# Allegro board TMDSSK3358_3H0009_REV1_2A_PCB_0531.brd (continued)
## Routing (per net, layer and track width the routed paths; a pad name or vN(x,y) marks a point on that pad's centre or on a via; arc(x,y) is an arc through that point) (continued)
MMC1_D2: length 76.1
  LY6_SIG2 w0.127: v2(68.74,31.41) 68.6,31.41 68.2,31.01 67.78,31.01 67.55,30.78 67.55,30.35 67.4,30.2 67.4,28.76 66.83,28.19 66.83,25.9 66.78,25.85 66.78,25.81 63.37,22.39 62.7,22.39 61.29,20.99 60.15,20.99 59.04,19.88 54.45,19.88 52.16,22.17 49.02,22.17 35.53,22.17 32.66,25.05 32.66,25.28 29.71,28.22 29.71,29.57 28.4,30.88 28.4,33.53 26.75,35.19 23.25,35.19 22.92,34.86 22.92,33.22 22.54,32.84 v1(15.37,32.84)
  BOTTOM w0.14: R185.1 16.21,36.14 14.9,34.84 A1.14 14.9,33.31 v1(15.37,32.84) ; U26.R8 v2(68.74,31.41)
MMC1_D3: length 75.3
  LY6_SIG2 w0.127: v1(20.53,35.13) 19.95,34.54 18.57,34.54 18.31,34.29 18.31,33.76 18.57,33.5 21.69,33.5 22.26,34.07 22.26,35.47 22.64,35.85 28.05,35.85 29.85,34.05 29.85,31.69 31.74,29.8 31.74,29.12 32.58,28.29 33.34,28.29 34.13,27.5 34.13,25.34 36.63,22.83 44.46,22.83 45.24,23.61 45.61,23.61 46.38,22.83 53,22.83 55.21,20.62 57.03,20.62 58.31,21.91 61.28,21.91 63.59,24.22 64.32,24.22 65.67,25.56 65.67,27.23 66.33,27.89 66.33,31.04 66.69,31.41 v2(67.94,31.41)
  BOTTOM w0.14: A1.19 19.9,34.5 v1(20.53,35.13) 19.9,35.75 19.9,35.9 R182.1 ; U26.T8 v2(67.94,31.41)
Net_4: length 0.5
  BOTTOM w0.127: 104.75,30.17 104.89,30.17 105.14,29.92
Net_5: length 0.5
  BOTTOM w0.127: 104.75,30.93 104.89,30.93 105.16,31.21
Net_6: length 0.5
  BOTTOM w0.127: 58.77,14.63 58.91,14.63 59.17,14.38
Net_7: length 0.5
  BOTTOM w0.127: 58.77,15.38 58.91,15.38 59.19,15.66
Net_14: length 0.6
  BOTTOM w0.14: 78.74,30.21 78.74,30.21 v2(79.14,29.81)
NON_REM1: length 3.3
  BOTTOM w0.14: U16.13 42.82,53.15 42.6,52.93 R118.1 R119.2
NON_REM2: length 10.2
  TOP w0.14: v1(35.97,58.65) 37.58,58.65 39,57.22 39.97,57.22 v1(40.04,57.29) 40.04,56.37 R12.2 R13.1
  BOTTOM w0.14: TP1.1 34.97,58.65 v1(35.97,58.65) ; v1(40.04,57.29) U16.19
PHY2_LED_10/100N: length 4.2
  BOTTOM w0.14: C237.1 59.49,34.65 58.65,35.48 58.02,35.48 57.43,36.08 U24.26
PHY2_LED_1000N: length 44.2
  TOP w0.14: v1(63.37,57.96) 62.82,58.52 R9.1 ; R61.2 59.31,36.28 59.55,36.53 59.55,36.54 ; 59.55,36.54 59.51,36.58 58.42,36.58 C81.1 ; 59.55,36.54 v1(59.55,36.7)
  LY6_SIG2 w0.127: v1(63.37,57.96) 62.71,58.62 61.66,58.62 58.77,55.73 57.79,55.73 55.26,53.2 55.26,50.18 50.93,45.86 50.93,41.74 52.11,40.56 52.11,39.76 54.03,37.85 57.46,37.85 58.6,36.7 v1(59.55,36.7)
  BOTTOM w0.14: U24.24 58.7,36.93 59.05,36.58 59.51,36.58 59.55,36.54 v1(59.55,36.7)
PHY2_LED_ACTN: length 40.9
  TOP w0.14: C68.1 59.44,37.47 v1(59.52,37.38) 60.07,36.83 60.07,36.2 R62.2 ; v1(62.1,57.96) 61.68,58.39 R8.1
  LY6_SIG2 w0.127: v1(59.52,37.38) 59.51,37.38 59.47,37.34 58.7,37.34 56.93,39.12 54.03,39.12 53.75,39.4 53.32,39.83 53.2,39.95 52.89,40.26 52.89,41.93 51.31,43.51 51.31,45.7 55.64,50.03 55.64,52.99 57.79,55.14 59.28,55.14 v1(62.1,57.96)
  BOTTOM w0.14: v1(59.52,37.38) 59.52,37.67 59.24,37.95 U24.23
PHY_LED_10/100N: length 6.5
  BOTTOM w0.14: U23.26 97.81,36.13 98.46,35.48 99.32,35.48 100.81,33.99 102.02,33.99 C240.1
PHY_LED_1000N: length 39.5
  TOP w0.14: R7.1 94.47,62.43 94.47,58.4 96.91,55.95 99.69,55.95 102.11,53.53 v1(102.11,52.07) ; R60.2 100.79,36.37 100.59,36.58 v1(99.95,36.58)
  LY3_SIG1 w0.127: v1(99.95,36.58) 100.5,36.58 102.11,38.19 102.11,48.64 103.36,49.89 103.36,52.16 103.1,52.42 102.46,52.42 v1(102.11,52.07)
  BOTTOM w0.14: U23.24 99.56,37.55 99.83,37.28 99.83,36.7 v1(99.95,36.58) 100.62,36.58 100.79,36.4 C229.1
PHY_LED_ACTN: length 51
  TOP w0.14: v1(100.48,37.19) 100.48,37.24 100.71,37.47 R53.2 ; v1(102.92,51.98) 102.9,51.99 102.9,53.9 99.94,56.86 96.88,56.86 95.26,58.48 95.26,63.83 93.41,65.68 84.15,65.68 R6.1
  LY3_SIG1 w0.127: v1(100.48,37.19) 101.68,38.39 101.68,50.74 v1(102.92,51.98)
  BOTTOM w0.14: U23.23 99.72,37.95 v1(100.48,37.19) 101,37.19 R53.2
PHY_PPS2/GPIO: length 2
  BOTTOM w0.14: U24.22 59.31,38.35 R181.1
PHY_PPS/GPIO: length 2.5
  BOTTOM w0.14: U23.22 100.01,38.35 100.26,38.1 100.77,38.1 R176.1
PLLFILT: length 2
  TOP w0.14: v1(43.82,60.2) 43.87,60.14 C7.1
  BOTTOM w0.14: U16.25 v1(43.82,60.2)
PMIC_GPIO: length 2.4
  TOP w0.14: v1(109.98,37.21) 110.19,37.41 110.41,37.41 R59.2
  BOTTOM w0.14: v1(109.98,37.21) 109.98,37.34 110.49,37.84 U25.39
PMIC_GPIO_RTC: length 4.1
  BOTTOM w0.14: U19.6 112.53,52.83 R108.1 C191.1 R107.1
PMIC_I2C_SCL: length 3
  BOTTOM w0.14: U25.9 115.05,42.79 115.44,43.19 R139.1
PMIC_I2C_SDA: length 3.3
  BOTTOM w0.14: U25.8 114.65,42.86 115.04,43.26 115.04,44.34 R140.1
PMIC_INT1: length 15.7
  TOP w0.14: v1(106.4,42.9) 107.03,42.27 108.33,42.27 108.78,42.72 108.78,43.25 108.97,43.43 109.6,43.43 R28.1
  BOTTOM w0.14: R128.1 106.31,44.22 105.89,43.79 105.89,43.3 106.28,42.9 v1(106.4,42.9) 106.6,42.7 106.6,41.76 107.24,41.12 107.75,41.12 108.55,40.33 109.87,40.33 109.96,40.24 U25.45
PMIC_PWRHOLD: length 4.9
  TOP w0.14: R27.1 108.9,44.15 v1(108.81,44.07)
  BOTTOM w0.14: U25.1 110.59,42.22 108.81,43.99 v1(108.81,44.07)
PMIC_RESETOUTN: length 43
  TOP w0.14: R49.2 109.35,38.34 v1(109.73,37.96)
  LY6_SIG2 w0.127: v1(109.73,37.96) 110.03,37.66 110.17,37.66 110.8,37.03 110.8,34.81 110.23,34.25 109.6,34.25 107.3,31.94 103.53,31.94 103.02,32.45 101.82,33.65 93.43,33.65 92.25,34.82 90.98,34.82 88.77,37.03 88.77,37.47 88.37,37.86 87.43,37.86 86.91,37.34 v2(84.96,37.34)
  BOTTOM w0.14: v1(109.73,37.96) 110.15,37.96 110.43,38.24 U25.40 ; U26.B15 79.95,37.83 82.13,37.83 82.63,38.33 83.22,38.33 84.33,37.21 84.84,37.21 v2(84.96,37.34)
PMIC_SLEEP: length 7.2
  BOTTOM w0.14: TP9.1 106.04,34.35 108.46,34.35 109.11,35 109.11,35.57 109.24,35.7 110.58,37.04 U25.37
PMICSR_I2C_SCL: length 3.6
  BOTTOM w0.14: R137.1 117.73,45.06 117.25,44.58 117.25,44.06 115.85,42.66 U25.11
PMICSR_I2C_SDA: length 3.3
  BOTTOM w0.14: U25.10 115.45,42.72 116.59,43.86 R138.1
PWR_SMPS1: length 1.8
  BOTTOM w0.203: 112.25,35.61 U25.35
  BOTTOM w0.381: 112.25,34.46 112.25,35.61
PWR_SMPS1_FB: length 35.7
  LY6_SIG2 w0.254: v1(99.45,26.11) 101.11,27.76 108.15,27.76 v1(113.66,33.27)
  BOTTOM w0.203: U25.32 113.45,34.54 113.75,34.24 114.15,34.24 114.43,33.97 R201.2
  BOTTOM w0.254: v1(99.45,26.11) 98.25,24.91 96.13,24.91 95.38,25.65 94.23,25.65 92.96,24.38 89.28,24.38 v1(88.14,23.24) 87.5,22.61 R223.2
  BOTTOM w0.381: R201.2 113.87,33.48 v1(113.66,33.27)
PWR_SMPS2: length 0.6
  BOTTOM w0.203: U25.42 110.43,39.04
PWR_SWIO: length 1.1
  BOTTOM w0.203: 117.61,41.04 U25.14
  BOTTOM w0.254: 118.14,41.04 117.61,41.04
PWR_VDDIO: length 4.1
  BOTTOM w0.14: U25.12 116.25,42.54 118.02,44.31 R144.2
REFIN_DDR: length 3.7
  TOP w0.14: R93.1 C171.1 R95.1 87.78,5.61 U14.1
RESETN: length 3.5
  BOTTOM w0.14: R106.1 C189.1 39.94,55.63 40.6,56.29 U16.17
RGMII1_INT: length 95.5
  TOP w0.14: v2(67.94,30.61) 66.73,29.4 66.73,26.62 67.2,26.14 68.3,26.14 69.03,25.41 69.03,24.89 68.88,24.74 68.88,20.18 69.35,19.72 80.07,19.72 80.29,19.93 81.17,20.81 83.04,20.81 85.89,20.81 86.36,21.28 93.3,21.28 93.57,21.54 93.57,21.55 93.67,21.64 93.74,21.72 94.49,22.46 95.39,22.46 v1(95.76,22.83)
  LY3_SIG1 w0.127: v1(95.76,22.83) 94.6,22.83 94.32,23.12 94.32,25.57 94.83,26.08 98.31,26.08 98.73,25.66 103.07,25.66 105.92,28.51 105.92,32.06 106.69,32.84 106.69,33.35 106.06,33.98 106.06,36.95 105.73,37.28 105.73,38.95 107.76,40.98 107.76,43.96 108.47,44.67 108.47,45.69 107.76,46.4 107.76,48.97 103.98,52.75 100.36,52.75 v1(97.47,49.86)
  BOTTOM w0.14: U26.U6 v2(67.94,30.61) ; R122.2 v1(97.47,49.86)
RGMII1_TXCLK: length 5.7
  BOTTOM w0.14: U26.K18 73.14,40.19 73.28,40.33 73.28,40.37 73.3,40.39 73.3,42.95 73.42,43.07 73.42,43.9 73.84,44.32 R134.2
RGMII1_TXD0: length 6.6
  BOTTOM w0.14: R135.2 72.83,42.91 72.89,42.85 72.89,42.84 73.06,42.66 73.06,40.49 72.77,40.2 72.77,39.38 U26.K17
RGMII1_TXD1: length 11.4
  LY6_SIG2 w0.127: v1(78.05,43.05) 78.05,41.5 77.61,41.05 76.25,41.05 76.06,40.86 74.19,40.86 72.74,39.41 v2(72.74,38.61)
  BOTTOM w0.14: v1(78.05,43.05) 78.05,44.27 78.29,44.5 R130.2 ; U26.K16 v2(72.74,38.61)
RGMII1_TXD2: length 11
  LY6_SIG2 w0.127: v1(71.23,44.65) 72.84,43.04 72.84,40.6 71.54,39.31 71.54,37.65 71.78,37.42 72.34,37.42 v2(72.74,37.81)
  BOTTOM w0.14: v1(71.23,44.65) 71.79,45.21 R136.2 ; U26.K15 v2(72.74,37.81)
RGMII1_TXD3: length 5.8
  BOTTOM w0.14: R133.2 74.93,44.67 74.21,43.95 74.21,42.84 74.23,42.82 74.23,42.48 73.94,42.19 U26.J18
RGMII1_TXEN: length 11.4
  LY6_SIG2 w0.127: v2(73.54,38.61) 74.51,38.61 76.66,40.76 78.43,40.76 78.84,41.17 78.84,41.65 78.5,41.99 78.5,42.69 v1(78.87,43.05)
  BOTTOM w0.14: v2(73.54,38.61) U26.J16 ; v1(78.87,43.05) 78.87,43.89 79.31,44.33 R129.2
RGMII2_INT: length 37
  TOP w0.14: v1(49.61,46.96) 49.34,47.24 49.11,47.24 48.7,47.65 48.7,48.77 R20.2
  LY3_SIG1 w0.127: v1(49.61,46.96) 49.83,46.75 49.83,46.65 50.48,46 51.59,46 52.96,47.37 53.89,47.37 54.08,47.56 55.14,47.56 55.85,46.85 59.1,46.85 59.26,46.69 63.09,46.69 66.42,43.36 66.42,41.85 67.31,40.96 71.57,40.96 71.78,41.16 74.53,41.16 76.74,38.95 v2(76.74,38.61)
  BOTTOM w0.14: U26.F16 v2(76.74,38.61)
RGMII2_TXCLK: length 8.1
  BOTTOM w0.102: U26.U15 67.07,37.88 66.6,37.88 66.25,38.23 65.91,38.23
  BOTTOM w0.14: 65.91,38.23 64.8,38.23 62.45,40.58 62.45,41.11 R168.2
RGMII2_TXD0: length 5.5
  BOTTOM w0.14: R174.2 62.14,37.87 64.07,37.87 64.52,37.41 66.3,37.41 66.3,37.41 U26.V15
RGMII2_TXD1: length 4.3
  TOP w0.14: v2(66.13,37.81) 65.52,37.81 R51.2
  LY6_SIG2 w0.127: v2(66.13,37.81) 66.93,37.01 v2(68.74,37.01)
  BOTTOM w0.14: U26.R14 v2(68.74,37.01)
RGMII2_TXD2: length 7.4
  BOTTOM w0.102: 65.66,36.61 66.27,36.61 66.6,36.94 68.01,36.94 U26.T14
  BOTTOM w0.14: R180.2 62.22,36.89 62.55,36.89 62.68,37.01 64.5,37.01 64.9,36.61 65.66,36.61
RGMII2_TXD3: length 8.9
  BOTTOM w0.14: R192.2 61.08,34.23 61.08,35.29 61.59,35.81 61.87,35.81 62.14,36.08 63.23,36.08 63.26,36.06 64.56,36.06 64.57,36.06 66.49,36.06 66.59,36.16 67.09,36.16 U26.U14
RGMII2_TXEN: length 4.7
  TOP w0.14: R56.2 65.72,36.55 66,36.55 66.13,36.68 v2(66.13,37.01)
  LY6_SIG2 w0.127: v2(68.74,36.21) 68.25,36.7 66.45,36.7 66.14,37.01 v2(66.13,37.01)
  BOTTOM w0.14: U26.R13 v2(68.74,36.21)
RSVD3: length 4.1
  BOTTOM w0.14: U16.15 41.42,53.68 40.82,53.09 39.55,53.09 R109.1
RTC_PORZ: length 54.5
  LY3_SIG1 w0.127: v1(107.31,47.12) 105.91,45.71 105.91,44.65 105.3,44.04 105.3,42.49 105.42,42.37 105.42,39.11 105.26,38.95 105.26,31.14 103.75,29.63 103.75,28.07 102.37,26.68 99.39,26.68 99.11,26.41 94.53,26.41 93.97,26.98 93.05,26.98 90.91,29.12 90.15,29.12 89,30.27 v1(87.69,30.27)
  BOTTOM w0.14: U26.B5 79.94,29.81 82.21,29.81 82.52,29.5 86.73,29.5 87.5,30.27 v1(87.69,30.27) ; v1(107.31,47.12) 107.58,47.38 111.78,47.38 112.02,47.62 R125.2 112.53,47.63 U19.3
RTCK: length 7.1
  TOP w0.14: v1(95.97,7.31) R92.1
  BOTTOM w0.14: J12.9 98.63,5.55 97.88,6.29 96.99,6.29 v1(95.97,7.31)
SS: length 4.9
  TOP w0.14: R48.1 23.89,40.7 23.89,40.64 24.03,40.5 R50.2 24.28,39.7 25.41,39.7 25.67,39.95 U7.3
SW3: length 1.5
  BOTTOM w0.14: U25.31 113.85,35.53 113.97,35.41 v1(113.97,34.8)
SYS_WARMRESETN: length 251.1
  TOP w0.14: R17.1 v1(38.28,50.27) ; v1(34.63,14.94) 34.93,15.24 R87.2 ; v1(105.04,5.91) 102.82,3.69 98.58,3.69 R97.2 ; v1(127.41,12.19) 125.01,12.19 122.82,14.39 122.82,15.93 121.62,17.13 115.42,17.13 114.01,18.54 111.49,18.54 111.49,18.54 107.65,18.54 107.12,19.07 v1(107.12,19.69) 106.75,20.05 106.75,24.13 107.12,24.5 107.12,27.98 104.25,30.85 104.25,33.46 103.89,33.83 103.89,37.69 102.09,39.48 102.09,45.52 99.76,47.85 96.46,47.85 96.05,48.26 v1(86.93,48.26) 86.61,47.95 U6.2
  LY3_SIG1 w0.127: v1(105.04,5.91) 105.04,10.61 105.42,10.99 105.42,17.98 107.12,19.67 v1(107.12,19.69) 105.23,21.57 94.68,21.57 93.26,22.99 93.26,25.26 93.08,25.44 90.4,28.12 89.76,28.12 88.67,29.21 87.4,29.21 86.36,30.25 86.36,32.21 v2(84.72,33.85) ; v1(34.63,14.94) 34.63,17.3 35.33,18.01 35.33,23.27 36.07,24.01 37.72,24.01 38.67,24.96 38.67,25.88 38.72,25.92 38.72,26.59 37.67,27.63 37.01,27.63 36.74,27.89 36.74,28.57 36.24,29.07 36.24,30.07 34.84,31.47 34.84,33.9 32.67,36.07 31.24,36.07 30.63,36.68 30.63,37.52 30.63,38.83 30.11,39.35 30.11,40.28 29.18,41.21 29.18,41.74 29.34,41.9 29.34,44.87 34.73,50.27 v1(38.28,50.27)
  BOTTOM w0.14: v1(38.28,50.27) 39.23,50.27 39.55,49.94 44.03,49.94 44.82,50.73 46.23,50.73 46.8,51.3 49.71,51.3 50.15,50.86 54.04,50.86 55.48,52.31 55.48,54.4 57.72,56.64 67.93,56.64 70.17,58.87 72.58,58.87 76.87,54.59 76.87,49.95 77.81,49 78.34,49 79.15,49.81 85.38,49.81 v1(86.93,48.26) ; C279.1 127.33,9.53 SW7.3 v1(127.41,12.19) SW7.4 ; R191.1 85.73,33.85 v2(84.72,33.85) 84.66,33.91 84.13,33.91 83.79,33.57 83.36,33.57 83.2,33.73 82.73,33.73 82.41,33.41 81.51,33.41 81.49,33.43 80.35,33.43 U26.A10
TCK: length 6.9
  TOP w0.14: v1(94.83,7.31) R91.1
  BOTTOM w0.14: J12.11 97.36,5.55 96.99,5.91 96.23,5.91 v1(94.83,7.31)
TDIS: length 6.4
  BOTTOM w0.14: R236.2 103.25,14.24 102.56,13.55 102.56,9.3 J12.4
USB0_DM: length 41.3
  LY3_SIG1 w0.127: v2(70.35,42.68) 70.35,42.43 70.26,42.34 70.04,42.34 69.91,42.47 69.91,47.14 66.63,50.42 58.42,50.42 57.99,50.85 57.99,51.8 57.32,52.48 56.36,52.48 54.74,50.86 53.68,50.86 53.4,51.14 53.4,51.44 v1(53.59,51.63)
  BOTTOM w0.127: v2(70.35,42.68) 70.74,42.29 70.74,41.72 70.6,41.58 70.6,39.95 U26.N18 ; U16.2 46.56,57.79 46.67,57.68 47.57,57.68 48.37,56.88 49.51,56.88 49.77,56.61 52.18,56.61 53.24,55.55 53.24,51.98 v1(53.59,51.63)
USB0_DP: length 41.2
  LY3_SIG1 w0.127: v2(70.34,41.88) 70.14,42.09 69.93,42.09 69.65,42.37 69.65,47.03 66.52,50.17 58.32,50.17 57.74,50.74 57.74,51.7 57.21,52.23 56.47,52.23 54.85,50.61 53.57,50.61 53.15,51.04 53.15,51.52 53.04,51.63 v1(52.74,51.63)
  BOTTOM w0.127: v2(70.34,41.88) 70.34,41.78 70.35,41.78 70.35,39.44 70.74,39.05 U26.N17 ; v1(52.74,51.63) 52.99,51.88 52.99,55.44 52.07,56.36 49.67,56.36 49.4,56.62 48.27,56.62 47.46,57.43 46.79,57.43 46.78,57.42 46.7,57.42 46.56,57.29 U16.3
USB0_ID: length 18.5
  LY6_SIG2 w0.127: v1(70.44,50.01) 70.46,50 70.46,49.4 68.4,47.35 68.4,44.78 66.78,43.15 66.78,42.57 67.09,42.26 67.09,41.02 67.44,40.67 68.66,40.67 69.54,39.78 v2(69.54,38.61)
  BOTTOM w0.14: U26.P16 v2(69.54,38.61) ; v1(70.44,50.01) 71.81,50.01 72.04,49.78 TP4.1
USB0_VBUS: length 66.6
  TOP w0.381: U5.4 40.35,52.48 v1(40.06,52.2)
  TOP w0.508: v1(40.06,52.2) R15.1 ; v1(71.13,51.54) 71.21,51.62 C18.1
  LY6_SIG2 w0.508: v1(71.13,51.54) 70.9,51.54 69.73,50.37 69.73,49.59 67.8,47.67 67.8,46.96 67.8,45.09 66.18,43.47 66.18,42.49 66.47,42.2 66.47,40.39 67.56,39.3 67.56,39.17
  LY6_SIG2 w0.635: v1(71.13,51.54) 71.23,51.64 71.23,51.67 72.8,53.25 72.8,54.15 72.29,54.66 72.29,55.06 71.78,55.58 69.5,55.58 64.6,60.47 61.56,60.47 56.43,55.35 52.53,55.35 51.49,56.39 49.81,56.39 48.56,57.63 46.51,57.63 45.39,58.75 42.39,58.75 41.61,57.97 41.61,53.75 v1(40.06,52.2)
  BOTTOM w0.305: v2(69.54,37.81) 69.54,37.81 69.93,37.41 U26.P15
USB0_VBUS_PWR: length 2.2
  TOP w0.14: U5.3 43.75,53.15 v1(43.43,53.47)
  BOTTOM w0.14: U16.11 43.82,53.85 v1(43.43,53.47)
USB1_CONN_DM: length 6.2
  BOTTOM w0.127: L2.3 25.91,54.52 25.61,54.81 24.02,54.81 U17.2 23.7,54.69 23.45,54.94 23.45,57.42 J5.2
USB1_CONN_DP: length 6.2
  BOTTOM w0.127: J5.3 23.95,58.01 23.83,57.89 23.83,57.65 23.7,57.53 23.7,55.37 U17.1 24.01,55.07 25.61,55.07 25.91,55.37 L2.4
USB1_DM: length 54.7
  LY3_SIG1 w0.127: v2(68.75,43.08) 68.8,43.13 68.8,46.81 66.2,49.4 56.89,49.4 56.44,49.85 54.81,49.85 54.38,49.42 53.31,49.42 53.3,49.4 47.58,49.4 45.6,51.38 36.65,51.38 36.45,51.59 36.04,51.59 v1(35.58,51.13)
  BOTTOM w0.127: v2(68.75,43.08) 68.76,43.07 68.76,42.73 69.14,42.35 69.14,41.87 69,41.73 69,39.95 U26.R18 ; v1(35.58,51.13) 35.76,51.31 35.76,54.3 34.93,55.14 32.71,55.14 32.38,54.81 28.53,54.81 28.23,54.52 L2.2
USB1_DP: length 54.7
  LY3_SIG1 w0.127: v2(68.75,42.16) 68.75,42.49 68.33,42.91 68.33,43.25 68.54,43.47 68.54,46.7 66.1,49.15 56.99,49.15 56.78,49.15 56.34,49.59 54.92,49.59 54.48,49.16 53.42,49.16 53.4,49.15 53.19,49.15 47.48,49.15 45.5,51.13 v1(36.21,51.13)
  BOTTOM w0.127: U26.R17 69.12,39.01 68.75,39.39 v2(68.75,42.16) ; v1(36.21,51.13) 36.02,51.33 36.02,54.41 35.03,55.39 32.6,55.39 32.28,55.07 28.53,55.07 28.23,55.37 L2.1
USB1_ID: length 6.3
  BOTTOM w0.14: U26.P17 69.53,39.43 69.53,44.45 R143.2
USB5V_FB: length 5.3
  TOP w0.14: v1(21.16,47.32) 20.53,47.32 20.02,47.83 20.02,49.61 R18.2 R19.1
  BOTTOM w0.14: v1(21.16,47.32) 21.29,47.45 21.42,47.45 21.6,47.63 U20.E3
USB_DC: length 17.3
  TOP w0.508: v1(40.34,64.97) 40.01,64.64 C2.1 40.01,62.77 39.54,62.3 37.76,62.3 35.07,59.61 35.07,57.73 35.9,56.9 v1(37.56,56.9)
  BOTTOM w0.254: C188.1 40.08,64.22 U15.6
  BOTTOM w0.381: J3.1 40.68,65.31 v1(40.34,64.97) 39.96,64.59 C188.1
  BOTTOM w0.508: v1(37.56,56.9) 37.69,56.77 R103.2
USBDM_UP: length 6.2
  BOTTOM w0.127: J3.2 41.33,65.42 41.53,65.22 41.53,64.1 40.36,62.94 39.71,62.94 39.58,62.81 U15.2 39.73,62.35 39.73,62.04 39.41,61.72 L1.3
USBDP_UP: length 6.2
  BOTTOM w0.127: L1.4 40.26,61.68 40.58,62 40.58,62.12 40.48,62.23 40.17,62.23 39.99,62.41 U15.1 40.26,62.69 40.47,62.69 41.78,64 41.78,65.22 41.98,65.42 J3.3
VADDL_PHY: length 24.7
  TOP w0.381: C54.1 92.77,45.32 94.57,47.12 95.7,47.12 96.46,46.35 97.5,46.35 98.48,45.37 98.48,43.12 v1(99.09,42.52)
  TOP w0.508: C48.1 99.06,42.49 v1(99.09,42.52) ; C54.1 v1(91.62,40.89) ; C66.1 99.42,39.62 99.49,39.55 v1(99.9,39.55) ; v1(96.77,44.45) 96.77,44.04 96.65,43.92 C40.1
  BOTTOM w0.203: v1(91.62,40.89) 92.17,40.35 U23.44 ; v1(99.09,42.52) 99.53,42.52 99.75,42.29 99.75,42.04 99.67,41.95 U23.13 ; U23.8 96.61,44.08 96.77,44.25 v1(96.77,44.45) ; U23.19 v1(99.9,39.55)
  vias: v1(87.66,41.83) v1(88.44,41.8)
VADDL_PHY2: length 29.6
  TOP w0.508: C36.1 56.03,43.28 56.03,44.48 v1(56.45,44.96) ; v1(51.54,40.16) 51.77,40.39 C58.1 ; C47.1 v1(58.67,42.55)
  LY3_SIG1 w0.381: v1(51.54,40.16) 51.67,40.03 51.74,40.03 52.7,39.07 57.55,39.07 58.04,39.55 v1(59.49,39.55)
  LY6_SIG2 w0.508: v1(51.54,40.16) 49.29,42.41 49.29,45.51 48.53,46.27 48.53,47.27 46.93,48.87 v1(45.35,48.87)
  BOTTOM w0.203: U24.13 58.7,42.52 v1(58.67,42.55) ; U24.44 51.74,40.35 v1(51.54,40.16) ; U24.19 v1(59.49,39.55) ; v1(56.45,44.96) 56.19,44.7 56.19,43.31 56.23,43.27 U24.8
  vias: v1(44.83,49.23) v1(45.35,49.6)
VAUX1: length 101.3
  TOP w0.381: v2(70.34,38.61) 70.34,39.07 70.16,39.24 C55.1 C56.1
  TOP w0.508: v1(108.2,42.85) 108.2,43.71 107.21,44.71 106.7,44.71 105.52,45.89 105.52,47.16 106.44,48.08 106.44,52.14 106.65,52.36 106.65,54.09 105.06,55.68 v1(105.06,57.56) 105.06,58.04 v1(104.84,58.25)
  LY3_SIG1 w0.508: v1(105.06,57.56) 105.06,58.04 v1(104.84,58.25) 104.84,62.4 104.31,62.94 103.39,62.94 101.83,61.38 95.63,61.38 92.84,64.17 92.84,65.79 91.57,67.06 77.34,67.06 76.22,65.93 76.22,59.31 v1(75.41,58.5) v1(74.3,58.5)
  LY5_PWR2 w0.508: v2(70.34,38.61) 70.34,38.86 69.93,39.27 69.09,39.27 68.74,38.92 v2(68.74,38.61)
  LY6_SIG2 w0.254: v1(74.3,58.5) 74.3,57.33 76.59,55.05 76.59,54.03 74.5,51.95 74.5,50.43 73.64,49.56 72.81,49.56 71.07,47.82 71.07,47 69.41,45.33 69.41,40.91 70.34,39.98 v2(70.34,38.61)
  LY6_SIG2 w0.381: v1(74.3,58.5) v1(75.41,58.5)
  BOTTOM w0.203: U25.46 110.01,40.64 109.81,40.84 109.34,40.84
  BOTTOM w0.305: U26.N16 v2(70.34,38.61) ; v2(68.74,38.61) U26.R16
  BOTTOM w0.381: v1(108.2,42.85) 108.2,42.06 C221.1 108.25,41.35 108.76,40.84 109.34,40.84
VAUX2: length 27.2
  TOP w0.508: 83.33,48.71 84.26,49.65 95.48,49.65 96.54,48.59 100.85,48.59 102.67,46.77 102.67,45.09 104.2,43.56 C31.1 105.18,43.56 105.32,43.7 106.17,43.7 106.31,43.56 v1(106.48,43.56)
  vias: v1(106.99,44) v1(107.09,43.37)
VAUX33: length 36.4
  TOP w0.508: R28.2 110.72,45.97 v1(110.41,45.67) 109.86,45.67 109.43,46.1 R27.2 ; v1(108.46,26.04) 108.46,24.06 107.58,23.19 107.58,20.12 107.75,19.95 107.75,19.95 108.14,19.56 108.58,19.12 114.8,19.12 115.94,17.98 122.74,17.98 v1(125.22,15.49)
  BOTTOM w0.203: 113.01,43.11 113.05,43.07 U25.4
  BOTTOM w0.254: 113.01,43.11 113.01,43.33 112.49,43.84 111.75,43.84 111.64,43.94 111.12,43.94 v1(111,44.07)
  BOTTOM w0.381: C212.1 110.2,44.74 110.33,44.74 v1(111,44.07)
  BOTTOM w0.508: v1(118.24,45.59) 118.73,45.59 R144.1 v1(119.25,47.19) ; R240.2 v1(125.22,15.49)
  vias: v1(98.82,11.63) v1(99.58,11.63) v1(101.23,11.63) v1(101.87,11.63) v1(107.95,26.54) v1(108.76,26.7)
VCOM_BAT: length 0.9
  BOTTOM w0.508: R224.2 27.26,21.92
  vias: v1(15.83,44.78) v1(16.59,44.78) v1(18.19,44.58) v1(27.9,26.11) v1(27.9,25.22) v1(28.4,24.33) v1(28.4,23.44)
VCOM_BATFB: length 4.4
  BOTTOM w0.508: R224.1 C257.2 26.5,24.21 R222.2 26.63,25.35 U27.5
VDAC: length 15.4
  TOP w0.508: C61.1 81.72,39.12 v1(81.97,39.37) 82.23,39.12 C62.1 84.23,37.62 84.23,35.78 84.83,35.18 84.99,35.18 v1(85.22,34.95) 85.37,34.8 C87.1
  LY5_PWR2 w0.381: 76.89,37.97 76.89,37.66 v2(77.54,37.01)
  BOTTOM w0.203: U25.22 118.49,37.84
  BOTTOM w0.254: v2(77.54,37.01) 77.14,36.61 U26.E14
  BOTTOM w0.305: v2(69.54,37.01) U26.P14 ; U26.E6 v2(76.74,29.81) ; U26.K13 v2(72.74,36.21) ; v2(69.54,32.21) U26.P9 ; v2(75.94,32.21) U26.F9 ; v2(71.14,29.81) U26.N6
  BOTTOM w0.508: v1(85.22,34.95) 85.52,35.25 C236.1
  vias: v1(84.19,41.42) v1(84.79,41.12) v1(85.3,40.66) v1(120.43,38.76) v1(120.45,38.07)
VDIG1: length 139.4
  LY6_SIG2 w0.635: v1(113.47,45.08) 114.93,43.62 119.15,43.62 125.08,37.69 125.08,20.37 117.7,12.99 117.7,2.01 v1(117.54,1.85)
  BOTTOM w0.203: 114.53,43.61 114.53,43.29 114.25,43 U25.7
  BOTTOM w0.254: 57.19,24.88 v1(57.13,24.94)
  BOTTOM w0.381: v1(113.47,45.08) 113.47,45 114.53,43.94 114.53,43.61
  BOTTOM w0.508: v1(113.47,45.08) 113.42,45.14 112.7,45.14 C210.1
  BOTTOM w0.635: v1(57.19,24.15) 57.19,24.88
  BOTTOM w0.762: v1(57.19,24.15) 57.13,24.09 57.13,24.09 57.05,24.01 57.05,23.94 56.76,23.65 56.76,22.79 57.05,22.5 57.05,17.4 56.44,16.79 56.44,12.15 56.44,12.15 56.44,10.71 57.16,9.99 57.16,4.64 59.9,1.9 76.98,1.9 77.99,2.92 81.35,2.92 83.25,1.02 112.16,1.02 112.76,1.62 114.85,1.62
  vias: v1(113.48,45.79) v1(115.63,1.7) v1(116.51,1.77)
VDIG2: length 18.3
  TOP w0.381: 74.34,38.6 74.93,39.19 C53.1 ; 74.34,38.6 v2(74.34,37.81) ; 74.34,38.6 73.59,39.35 C59.1 ; C95.1 67.16,33.4 67.55,33.01 v2(68.74,33.01)
  TOP w0.508: v2(76.74,31.41) 76.74,32.21 v2(76.74,32.21) 77.44,32.21 C98.1 ; C72.1 C84.1 v1(85.15,35.94)
  BOTTOM w0.254: U25.5 113.45,43.76
  BOTTOM w0.305: v2(76.74,31.41) U26.E7 ; v2(68.74,33.01) U26.R10 ; U26.H15 74.74,37.41 v2(74.34,37.81) ; v2(76.74,32.21) U26.E9 U26.D10 ; v2(68.74,33.81) U26.R11
  BOTTOM w0.381: 113.45,43.76 113.45,44.07 113.13,44.39 112.16,44.39 v1(112.1,44.45)
  BOTTOM w0.508: C211.1 v1(111.82,45.08) 111.82,44.73 v1(112.1,44.45)
VETH2_AVDD_3_3: length 25.3
  TOP w0.381: v1(55.4,31.78) 55.54,31.64 55.54,31.61 55.96,31.2 56.16,31.19 60.58,31.19 62.27,32.88 62.27,33.4 61.26,34.41 61.26,36.19 60.62,36.83 60.62,37.77 61.09,38.25 61.09,39.02 61.45,39.37 61.45,41.05 60.99,41.52 60.99,44.55 59.82,45.71 v1(59.82,45.75)
  BOTTOM w0.203: 59.44,40.75 U24.16
  BOTTOM w0.381: 59.44,40.75 59.87,40.75 60.51,41.39
  BOTTOM w0.508: v1(55.4,31.78) 55.43,31.81 R196.1
VETH2_LX: length 1.8
  BOTTOM w0.203: 53.98,43.81 54.21,43.59 54.21,43.35 54.23,43.33 U24.3
  BOTTOM w0.381: 53.98,43.81 53.97,43.81 53.59,44.2 53.59,44.32
VETH2_VDDIO: length 3.1
  TOP w0.508: v1(56.23,35.81) 56.23,36.26 55.91,36.58 C71.1 R54.2
  BOTTOM w0.203: U24.29 v1(56.23,35.81)
VETH_AVDD_3_3: length 2.6
  BOTTOM w0.203: 99.79,40.75 U23.16
  BOTTOM w0.381: 99.79,40.75 100.5,40.75 101.33,41.58
VETH_LX: length 1.3
  BOTTOM w0.203: 94.36,43.87 94.57,43.65 94.57,43.37 94.61,43.33 U23.3
  BOTTOM w0.381: 94.36,43.87 94.27,43.96
VETH_VDDIO: length 17.4
  TOP w0.381: R30.2 90.93,43.56 91.63,42.86 91.63,41.85 90.87,41.08 90.87,39.72 91.65,38.94 92.38,38.94 94.75,36.58 R55.2
  TOP w0.508: R55.2 C73.1 96.45,36.14 v1(96.45,35.07) ; R30.2 90.35,44.9 R25.1
  BOTTOM w0.203: U23.29 96.61,35.63
  BOTTOM w0.381: v1(96.45,35.07) 96.69,35.3 96.69,35.56 96.61,35.63
VMMC: length 178.6
  TOP w0.305: v2(68.74,37.81) 68.74,37.82 68.31,38.24
  TOP w0.381: C78.1 70.38,37.77 v2(70.34,37.81) ; U7.6 29.62,38.46 29.34,38.18 v1(29.04,38.18)
  TOP w0.508: 60.75,17.38 v1(60.75,17.4) ; 60.75,17.38 60.76,17.37 61.46,17.37 63.28,19.19 65.31,19.19 65.36,19.14 80.31,19.14 81.41,20.23 86.32,20.23 ; 60.75,17.38 60.74,17.4 60.18,16.84 v1(58.69,16.84)
  LY3_SIG1 w0.508: v1(49.91,12.77) 49.42,12.28 v1(49.42,12.14) 48.7,11.42 48.68,11.42 48.68,9.01 49.21,8.48 49.21,5.45 46.63,2.87 44.52,2.87 43.7,3.7 40.6,3.7 40.54,3.64 35.93,3.64 33.36,6.22 33.36,9.05 v1(33.38,9.07) v1(33.38,9.75) 32.79,10.34 31.11,10.34 30.28,11.17 30.28,13.51 30.69,13.92 30.69,15.88 32.64,17.83 32.64,24.51 34.12,25.98 34.12,29.04 33.37,29.79 32.2,29.79 31.83,29.42 31.83,29.17 v1(31.39,28.73) v1(30.94,29.18) 29.04,31.08 v1(29.04,38.18) 28.53,38.68 26.09,38.68 22.69,42.08 22.69,48.3 v1(20.49,50.5)
  LY6_SIG2 w0.508: v1(49.42,12.14) 49.91,12.63 v1(49.91,12.77) 49.96,12.83 52.59,12.83 53.88,14.12 53.88,14.59 54.42,15.13 54.42,15.51 55.74,16.84 v1(58.69,16.84) 60.2,16.84 60.75,17.38 v1(60.75,17.4) ; v1(76.75,48.42) 77.23,47.94 v1(77.31,47.94) 80.28,47.94 81.82,46.4 85.11,46.4 86.85,44.65 91.67,44.65 93.45,42.88 93.45,40.84 93.9,40.39 97.55,40.39 98.32,39.61 98.32,39.22 99.54,38 100.83,38 102.38,39.55 102.38,41.89 104.27,43.79 105.43,43.79 107.07,45.44 v1(107.43,45.44) 107.56,45.44 v1(107.94,45.06)
  BOTTOM w0.203: 111.52,43.04 111.94,43.04 112.25,42.74 U25.2
  BOTTOM w0.305: v2(68.74,37.81) U26.R15 ; U26.N15 v2(70.34,37.81)
  BOTTOM w0.381: C213.1 108.81,45.08
  BOTTOM w0.508: 108.81,45.08 110.86,43.04 111.52,43.04 ; R120.2 v1(20.49,50.5)
  vias: v1(87.04,20.77) v1(86.96,20.14)
VPLL: length 42.3
  TOP w0.508: FB7.2 86.59,30.99 87.45,31.85 88.47,31.85 88.7,32.08 91.64,32.08 v1(92.25,32.69)
  LY6_SIG2 w0.508: v1(120.12,35.48) 120.12,35.48 120.12,35.35 v1(119.73,34.97) 117.51,34.97 116.89,35.59 113.39,35.59 112.14,34.33 112.14,33.29 109.71,30.86 104.28,30.86 103.62,30.2 103.1,30.2 102.5,30.79 102.5,31.54 101.74,32.31 100.2,32.31 98.87,30.99 93.27,30.99 92.65,31.61 92.64,31.61 92.25,31.99 v1(92.25,32.69)
  BOTTOM w0.508: v1(119.73,34.97) 120.12,35.35 v1(120.12,35.48) C232.1
VPP: length 0.6
  BOTTOM w0.14: U26.M5 v2(71.14,29.01)
VREFP_ADC: length 1.3
  BOTTOM w0.203: U26.B9 79.95,33.03 v2(80.7,33.03)
VRTC: length 48.3
  TOP w0.508: R59.1 110.73,36.06 110.73,35.56 v1(110.22,35.05) 110.18,35.01 v1(109.56,35.01)
  LYR4_PWR1 w0.381: v1(85.27,32.21) 85.02,32.46 82.06,32.46 80.91,31.31 79.04,31.31 v2(78.34,30.61)
  LY5_PWR2 w0.508: v1(85.27,32.21) 85.62,32.21 89.43,36.02 89.43,36.72 v1(89.77,37.06)
  LY6_SIG2 w0.508: v1(89.77,37.06) 90.07,36.76 v1(90.34,36.76) 90.96,36.76 91.3,37.11 93.64,37.11 95.51,35.24 95.51,35.11 96.26,34.36 99.7,34.36 100.22,34.87 109.42,34.87 v1(109.56,35.01)
  BOTTOM w0.254: U19.5 112.03,52.31 111.76,52.58 111.38,52.58 111.12,52.83 111.14,52.83 111.14,52.82 v1(111.14,52.82) 110.87,53.1 R108.2 ; U19.8 113.53,52.82 C192.1
  BOTTOM w0.305: U26.D7 v2(78.34,30.61)
  BOTTOM w0.381: C192.1 v1(115.19,53.59) ; R175.2 49.59,38.98 v1(49.59,39.52)
  BOTTOM w0.508: C239.1 85.98,32.96 85.27,32.25 v1(85.27,32.21) ; R178.1 88.83,37.56 89.33,37.06 v1(89.77,37.06) 90.04,37.06 v1(90.34,36.76)
  vias: v1(119.25,50.55) v1(120.14,51.44) v1(120.14,50.55) v1(120.59,51.88) v1(120.9,50.46)
VRTC_PMIC: length 4.9
  BOTTOM w0.203: 117.88,38.89 117.73,39.04 U25.19 ; 114.65,35.47 U25.29
  BOTTOM w0.381: 117.88,38.89 118.29,38.48 v1(118.49,38.48) ; C238.1 115.53,33.98 v1(115.14,34.37) 114.65,34.86 114.65,35.47
  vias: v1(120.9,48.26) v1(120.9,47.37)
VTT_DDR: length 3.7
  TOP w0.254: U14.5 86.15,2.3 85.94,2.51 ; U14.3 86.11,3.3 86.06,3.35
  vias: v1(86.99,14.61) v1(86.99,13.84) v1(86.98,13.21) v1(87.11,12.42)
VUSB_VBUS1: length 8.5
  LY3_SIG1 w0.635: 20.37,57.12 J5.1 ; J5.1 19.48,58.01 ; J5.1 21.26,58.01 ; J5.1 20.37,58.89
  BOTTOM w0.254: C190.1 21.68,55.19
  BOTTOM w0.305: 21.68,55.19 U17.6
  BOTTOM w0.635: J5.1 21.26,58.01 ; J5.1 19.48,58.01 ; J5.1 20.37,57.12 ; J5.1 20.37,58.89
  vias: v1(69.42,54.79) v1(69.72,54.23) v1(69.72,53.57)
WOL_INT2: length 4.7
  BOTTOM w0.14: U24.40 51.03,38.75 50.93,38.65 R175.1 50.53,38.26 50.26,38.26 50.24,38.24 49.78,37.79 49.78,37.14 49.84,37.09 49.84,36.97 49.84,36.96 49.87,36.93 R189.1
WOL_INT_1: length 4.6
  BOTTOM w0.14: U23.40 92.27,38.75 92.03,38.99 91.48,38.99 90.99,38.5 90.33,38.5 R173.1 R178.2
XTALIN: length 11.3
  TOP w0.14: R10.2 C6.2 v1(48.77,58.33)
  BOTTOM w0.14: v1(48.77,58.33) 48.77,59.19 Y3.3 46.4,61.55 44.38,61.55 43.32,60.49 U16.24
XTALIN_2: length 9.2
  TOP w0.14: v1(56.9,47.88) Y1.2 59.67,47.88 59.8,47.75 R24.1
  BOTTOM w0.14: v1(56.9,47.88) 56.9,46.36 C208.2 55.83,45.28 U24.7
XTALOUT: length 14.2
  TOP w0.14: v1(50.08,63.08) 50.08,62.59 49.78,62.29 C4.2 R10.1
  BOTTOM w0.14: U16.23 42.82,60.58 44.21,61.98 46.57,61.98 47.89,60.66 49.06,60.66 Y3.1 v1(50.08,63.08)
XTALOUT_2: length 6.8
  TOP w0.14: Y1.1 v1(55.63,47.88)
  BOTTOM w0.14: U24.6 55.43,44.82 55.12,45.13 C209.2 55.63,46.23 v1(55.63,47.88)
XTIN: length 9.9
  BOTTOM w0.14: Y5.3 44.42,39.46 45.59,38.28 C234.2 47.44,34.22 47.44,32.24 47.28,32.08 U28.2
XTOUT: length 8.5
  BOTTOM w0.14: Y5.1 46.96,37.25 46.74,37.03 C233.2 47.81,34.99 47.81,31.93 47.54,31.66 47.41,31.66 47.33,31.58 U28.3
N17107785: length 2.7
  BOTTOM w0.14: U25.18 117.97,39.44 118.29,39.12 118.74,39.12 C225.1
N17257600: length 10.5
  BOTTOM w0.14: U26.U9 67.12,32.2 65.66,32.2 65.34,32.52 64.52,32.52 63,30.99 63,27.89 R220.2
N17308459: length 6
  BOTTOM w0.14: R171.1 83.19,39.5 82.86,39.83 81.59,39.83 80.78,39.01 U26.A17
N17308818: length 3.3
  TOP w0.102: 79.26,36.61 78.74,36.61 v2(78.34,37.01)
  TOP w0.14: R52.2 79.97,37.24 79.97,36.98 79.6,36.61 79.26,36.61
  BOTTOM w0.14: U26.D14 v2(78.34,37.01)
N17308847: length 6
  BOTTOM w0.14: R186.2 85.53,36.7 83.83,36.7 83.12,37.41 U26.A15
N17365914: length 7.7
  BOTTOM w0.14: R132.2 76.26,43.9 75.87,43.51 74.99,43.51 74.73,43.26 74.73,43.26 74.73,42.8 75.19,42.34 75.19,39.36 U26.G17
N17619435: length 1.4
  BOTTOM w0.14: R181.2 60.33,34.99 TP8.1
N17619707: length 3.7
  BOTTOM w0.14: R169.2 50.17,40 50.17,39.63 50.52,39.27 51.88,39.27 52,39.15 U24.41
N17686170: length 14.6
  TOP w0.14: v1(88.22,28.52) 88.26,28.57 88.26,30.84 v1(88.38,30.96)
  BOTTOM w0.14: R210.1 R211.1 88.38,31.23 v1(88.38,30.96) ; v1(88.22,28.52) 87.9,28.21 87.44,28.21 87.17,28.47 82.39,28.47 81.85,29.02 79.13,29.02 U26.C5
N17710761: length 7.2
  BOTTOM w0.14: U26.J3 73.54,27.41 73.54,23.49 73.73,23.3 R226.2
N21001559: length 13.9
  TOP w0.14: v1(123.97,48.2) 123.97,46.68 R29.2
  BOTTOM w0.14: 124.62,49.12 SW6.3 SW6.4 ; 124.62,49.12 123.97,48.46 v1(123.97,48.2) ; 124.62,49.12 124.62,49.12 123.95,49.78 123.95,51.44 R117.1
N21001565: length 9.4
  BOTTOM w0.14: v1(128.78,45.12) 128.79,45.1 R167.2 R166.2 ; v1(128.78,45.12) SW6.2 ; v1(128.78,45.12) SW6.1
N21499158: length 12.1
  BOTTOM w0.14: U23.6 95.81,44.75 96.87,45.81 100.27,45.81 C202.2 101.31,46.86 101.31,48.58 100.79,49.1 Y4.1
N21499159: length 13
  BOTTOM w0.14: U23.7 96.21,44.56 97.05,45.39 101.07,45.39 C201.2 101.68,47.11 101.68,48.59 102.19,49.1 Y4.2
N21499217: length 1.1
  BOTTOM w0.14: R176.2 TP7.1
N21499246: length 4.4
  BOTTOM w0.14: U23.41 92.34,39.15 91.96,39.53 89.69,39.53 R170.2
N21689199: length 4
  TOP w0.14: R94.2 74.86,7.92 75.33,8.39 U32.L8 v2(76.31,8.8)
  BOTTOM w0.14: U32.L8 v2(76.31,8.8)
N21748558: length 5.7
  BOTTOM w0.14: TP10.1 82.06,26.54 81.29,27.32 80.84,27.32 U26.A3
N21748687: length 7.7
  BOTTOM w0.14: R218.2 82.62,27.43 81.81,28.24 79.91,28.24 U26.B4
N21817883: length 2.8
  TOP w0.14: D3.2 130.32,54.9 v1(130.32,53.97)
  BOTTOM w0.14: R113.1 130.05,53.97 v1(130.32,53.97)
N21817885: length 21.5
  TOP w0.14: D3.1 v1(130.43,58.42)
  BOTTOM w0.14: v1(130.43,58.42) 129.67,59.18 125.09,59.18 124.22,58.31 124.22,56.35 123.39,55.52 122.21,55.52 121.23,54.54 119.37,54.54 117.6,56.31 117.6,57.43 116.46,58.57 Q3.D
N21817914: length 21.6
  TOP w0.14: D4.1 v1(132.21,58.41)
  BOTTOM w0.14: Q2.D 117.34,63.88 118.54,63.88 119.18,64.52 123.49,64.52 125.45,62.56 125.45,60.02 125.78,59.69 130.92,59.69 v1(132.21,58.41)
N21817935: length 2.4
  TOP w0.14: D4.2 v1(132.21,53.85)
  BOTTOM w0.14: v1(132.21,53.85) R111.1
N21817961: length 15.5
  TOP w0.14: D2.1 v1(128.65,58.42)
  BOTTOM w0.14: v1(128.65,58.42) 128.02,57.78 126.36,57.78 125.35,56.77 125.35,55.75 123.44,53.85 117.97,53.85 117.6,54.22 Q5.D
N21817965: length 2.4
  TOP w0.14: D2.2 128.65,54.99 128.27,54.61 v1(128.27,53.85)
  BOTTOM w0.14: R114.1 128.27,53.34 v1(128.27,53.85)
N21817990: length 7.6
  TOP w0.14: D1.1 v1(126.87,58.42)
  BOTTOM w0.14: Q4.D 123.33,54.88 124.59,56.13 124.59,57.4 125.6,58.42 v1(126.87,58.42)
N21818011: length 3.3
  TOP w0.14: v1(125.6,54.99) 125.86,54.99 125.88,55.01 D1.2
  BOTTOM w0.14: R116.1 v1(125.6,54.99)
N21818396: length 2.3
  TOP w0.14: R74.1 103.73,28.42 103.5,28.19 U8.7
N21904036: length 1.5
  BOTTOM w0.203: U20.B2 U20.B1 22.9,49.12 23.32,49.54
N21904046: length 1.1
  BOTTOM w0.203: U20.D2 U20.D1 23.15,48.32
N21904056: length 2.4
  BOTTOM w0.102: U20.C4 U20.B3
  BOTTOM w0.14: U20.B3 U20.A3 21.6,50.44 C198.1 ; U20.D4 U20.C4
N21930375: length 1
  TOP w0.508: v1(13.29,22.3) 13.8,22.3 C136.1
  vias: v1(13.29,21.54) v1(13.29,20.78) v1(26.88,18.75) v1(26.88,17.86) v1(26.88,16.97)
N21930388: length 3.5
  BOTTOM w0.254: 14.43,31.09 A1.12
  BOTTOM w0.635: 14.43,31.09 13.65,31.09 13.23,31.5 13.23,33.48
N21930620: length 3.5
  BOTTOM w0.14: R187.1 R188.1 22.05,35.64 21.9,35.49 A1.21
N21930813: length 3.2
  BOTTOM w0.14: A1.40 18.8,18.13 R239.1
N21931209: length 1.7
  BOTTOM w0.14: L14.1 J10.4
N21931218: length 2
  BOTTOM w0.14: J10.1 R239.2
N21931238: length 3
  BOTTOM w0.14: L14.2 L13.1 L15.2
N22083094: length 18.7
  TOP w0.14: U10.9 94.32,15.77 v1(94.04,15.49)
  LY6_SIG2 w0.127: v1(90.23,8.3) 91.4,9.47 93.36,9.47 94.74,10.85 94.74,14.08 94.04,14.78 v1(94.04,15.49)
  BOTTOM w0.14: v1(90.23,8.3) 88.89,8.3 87.57,6.98 87.57,4.64 87.42,4.49 87.42,3.85 R244.1
N22083163: length 1.1
  TOP w0.14: R85.1 93.85,17.02 U10.7
N22104394: length 3.6
  BOTTOM w0.14: Y6.1 59.97,30.06 60.18,29.84 C245.2 R213.2 R216.1
N23618396: length 3.8
  BOTTOM w0.14: ANT1.1 L15.1
N23679698: length 4
  TOP w0.14: C181.2 54.13,4.42 v1(54.13,2.44)
  BOTTOM w0.14: J13.3 v1(54.13,2.44)
N23719034: length 1.8
  TOP w0.14: C146.1 43.88,14.22 v1(44.14,13.96)
  BOTTOM w0.14: U31.3 v1(44.14,13.96)
N23719056: length 2.4
  TOP w0.14: C150.1 45.03,13.59 v1(44.84,13.39)
  BOTTOM w0.14: U31.4 44.77,13.46 v1(44.84,13.39)
N23719058: length 1.7
  TOP w0.14: C153.1 43.43,12.96 v1(44.14,12.96)
  BOTTOM w0.14: U31.5 v1(44.14,12.96)
N23719070: length 2.3
  TOP w0.14: C155.1 45.55,12.41 v1(44.88,12.41)
  BOTTOM w0.14: U31.6 44.3,12.46 44.36,12.41 v1(44.88,12.41)
N23719098: length 2.5
  TOP w0.14: C163.1 45.65,10.16 45.35,10.46 v1(44.93,10.46)
  BOTTOM w0.14: U31.10 v1(44.93,10.46)
N23719102: length 1.8
  TOP w0.14: C161.1 35.43,10.67 v1(35.42,10.66)
  BOTTOM w0.14: U31.27 35.64,10.46 35.44,10.66 v1(35.42,10.66)
N23719106: length 2.5
  TOP w0.14: C157.1 35.69,11.68 v1(35.43,11.94)
  BOTTOM w0.14: v1(35.43,11.94) 35.43,11.34 35.81,10.96 U31.28
N23719110: length 1.7
  TOP w0.14: v1(44.14,10.96) 43.47,10.96 C160.1
  BOTTOM w0.14: U31.9 v1(44.14,10.96)
N23719153: length 2.4
  BOTTOM w0.14: U31.35 35.29,14.46 35.06,14.22 TP14.1
N23719155: length 2.7
  BOTTOM w0.14: U31.34 35.26,13.96 34.13,12.83 TP16.1
N23719175: length 1.8
  TOP w0.14: C164.1 43.83,9.65 v1(44.14,9.96)
  BOTTOM w0.14: U31.11 v1(44.14,9.96)
N23719177: length 5.4
  TOP w0.14: C166.1 42.93,8.64 v1(43.2,8.91)
  BOTTOM w0.14: v1(43.2,8.91) 43.2,8.14 42.88,7.82 42.21,7.82 42.08,7.95 U31.14
N23760521: length 1.7
  TOP w0.14: v1(44.14,11.96) 44.12,11.94 C156.1
  BOTTOM w0.14: U31.7 v1(44.14,11.96)
N23760525: length 2.4
  TOP w0.14: C159.1 45.47,11.42 v1(44.87,11.42)
  BOTTOM w0.14: v1(44.87,11.42) 44.29,11.42 44.25,11.46 U31.8
N23829528: length 1.7
  TOP w0.14: C162.1 26.78,11.1 U13.5
N24290596: length 5.8
  TOP w0.14: R88.2 R89.2 71.11,10.12 71.11,9.08 72.17,8.03 C167.1
N24349607: length 3.7
  TOP w0.14: R6.2 78.62,63.63 J6.D1
N24349674: length 2.7
  TOP w0.14: R7.2 93.14,64.78 J6.D4
N24351121: length 6.2
  TOP w0.14: J7.D1 56.59,63.58 R8.2
N24351236: length 7
  TOP w0.14: J7.D4 68.12,63.58 R9.2
N24874310: length 11.9
  TOP w0.14: v1(92.84,1.98) 92.84,2.59 92.34,3.08 92.34,3.67 R96.2 92.21,3.8 U14.9
  BOTTOM w0.14: v1(92.84,1.98) 91.69,1.98 91.31,2.36 87.64,2.36 85.68,4.32 TP23.1
N26901426: length 2.8
  TOP w0.14: D5.2 v1(126.11,13.75)
  BOTTOM w0.14: R240.1 126.07,13.72 v1(126.11,13.75)
N27067217: length 7.2
  BOTTOM w0.889: 111.2,16.18 J9.1 ; J9.1 114.61,12.77 ; J9.1 114.61,16.18
N27225292: length 10.7
  BOTTOM w0.14: Y7.1 91.96,28.81 91.96,27.93 92.38,27.51 92.38,25.19 92.08,24.89 89.66,24.89 89.03,25.53 C249.2 R217.2
N27258497: length 1.7
  BOTTOM w0.14: U19.7 113.02,53.59 R107.2
N27371597: length 14.4
  TOP w0.14: v1(47.58,9.22) 47.75,9.05 47.75,3.05 46.86,2.16 C185.2
  BOTTOM w0.14: J13.2 47.58,10.98 v1(47.58,9.22)
N27429071: length 14.5
  TOP w0.14: R80.1 57.44,22.12 57.44,21.01 58.23,20.22 60.49,20.22 60.64,20.37 60.64,20.78 61.96,22.09 63.99,22.09 64.3,21.79 65.82,21.79 66.51,22.48 J2.5
N27429091: length 15.2
  TOP w0.14: J2.6 67.51,22.49 66.45,21.42 63.99,21.42 v1(63.77,21.64) 62.02,21.64 61.01,20.63 61.01,20.22 60.65,19.85 58.08,19.85 57.74,20.19 57.11,20.19 R84.1
  BOTTOM w0.14: v1(63.77,21.64) 64.43,20.98 R225.1
N269460692: length 1.5
  TOP w0.14: R48.2 23.25,42.88 21.98,42.88 Q1.D
N2208308711: length 1.2
  TOP w0.14: R86.1 93.99,16.52 U10.8

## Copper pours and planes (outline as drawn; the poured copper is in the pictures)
AGND_AUD on TOP: 43.39,5.54 43.64,5.28 43.64,4.15 43.43,3.94 34.92,3.94 34.63,4.24 34.63,5.41 34.75,5.54
AGND_AUD on TOP: 36.83,13.9 36.83,9.56 37.12,9.27 42.67,9.27 42.67,14.43 42.3,14.81 39.44,14.81 37.51,16.74 37.51,17.54 36.63,18.41 34.8,18.41 34.86,18.36 34.86,16.87 35.97,15.75 35.97,15.65 35.95,15.62 35.95,14.78
AGND_AUD on BOTTOM: 42.05,5.46 47.62,5.46 48.26,4.83 48.26,1.4 48.01,1.14 45.34,1.14 42.67,3.81 40.39,3.81 40,4.19 40,5.33 40.58,5.91 41.6,5.91
AGND_AUD on LY3_SIG1: 37.55,4.14 39.13,4.14 39.24,4.25 39.22,4.27 42.87,4.27 43.45,4.85 43.45,6.07 45.05,7.67 46.47,7.67 47.71,8.9 47.71,12.14 48.34,12.78 48.34,13.41 47.61,14.14 46.53,14.14 46.18,13.79 44.41,13.79 43.65,14.55 35.82,14.55 34.91,13.64 34.88,13.64 34.88,10.87 34.19,10.18 34.19,7.5
DGND on TOP: 98.02,21.82 80.35,21.82 80.24,21.72 75.32,21.72 75.31,21.72 74.62,21.72 72.52,23.83 72.52,24.38 72.08,24.83 72.08,25.62 71.63,26.06 70.64,26.06 70.03,26.67 70.03,28.27 70.21,28.45 70.64,28.45 71.1,28.91 71.56,28.91 71.74,28.73 71.74,28.47 71.66,28.4 71.66,28.27 71.75,28.18 72.75,28.18 73.13,27.81 73.66,27.81 73.78,27.69 73.79,27.69 73.79,26.29 73.91,26.16 75.31,26.16 75.56,26.42 77.47,26.42 77.78,26.72 77.78,28.37 77.63,28.52 77.63,28.96 77.68,29.01 78.13,29.01 78.16,28.98 79.12,28.98 79.68,28.42 81.38,28.42 82.83,26.98 87.36,26.98 88.03,26.3 92.92,26.3 94.43,27.81 96.39,27.81 98.04,26.16 98.04,25.2 98.85,24.4 98.85,22.65
DGND on TOP: 88.52,2.16 88.52,6.98 88.7,7.16 89.32,7.16 90.56,5.91 90.56,5.53 90.04,5.01 90.04,2.16 90.68,2.16 90.93,1.9 90.93,1.52 90.8,1.4 90.79,1.41 89.78,1.41 89.71,1.35 88.77,1.35 88.75,1.37 87.91,1.37 87.76,1.52 87.76,2.03 87.88,2.16
DGND on TOP: 110.55,41.1 114.1,41.1 114.74,41.74 114.74,42.93 114.87,43.05 115.9,43.05 116.03,42.93 116.03,41.63 116.13,41.53 117.53,41.53 117.91,41.15 117.91,38 116.99,37.08 111.93,37.08 111.86,37.16 111.86,39.59 111.64,39.8 110.57,39.8 110.47,39.9 110.47,41.02
DGND on TOP: 112.2,52.69 112.2,48.06 111.72,47.57 110.66,47.57 110.65,47.58 109.87,47.58 109.5,47.96 109.5,48.65 109.62,48.77 110.44,48.77 110.62,48.95 110.62,49.65 111.18,50.22 111.18,52.35 110.12,53.41 108.34,53.41 106.82,54.94 106.82,60.02 107.46,60.65 114.19,60.65 114.69,60.14 114.69,53.74 114.24,53.28 112.79,53.28
DGND on TOP: 26.54,15.37 26.54,12.7 26.92,12.32 28.32,12.32 28.45,12.45 28.45,15.24 28.19,15.49 26.67,15.49
DGND on TOP: 51.12,51 51.12,45.79 52.01,44.9 54.12,44.9 55.31,46.1 57.57,46.1 57.9,45.77 58.2,45.77 58.46,46.02 60.97,46.02 61.09,46.13 61.24,46.13 61.56,46.45 61.56,51.1 60.67,51.99 52.21,51.99 51.22,51
DGND on TOP: 73.64,45.03 73.64,42.14 73.53,42.04 73.53,41.21 73.97,40.77 75.17,40.77 75.37,40.97 75.37,42.33 75.7,42.65 75.7,42.89 75.71,42.89 76.19,43.37 77.26,43.37 77.53,43.63 77.53,44.94 77.42,45.04 73.65,45.04
DGND on TOP: 27.39,38.68 27.39,41.66 26.88,42.17 26.88,44.15 27.01,44.27 29.42,44.27 29.55,44.15 29.55,42.11 28.91,41.48 28.91,38.68
DGND on TOP: 88.39,41.78 87.76,41.15 87.76,40.89 88.01,40.64 88.34,40.64 88.85,41.15 90.17,41.15 91.19,42.16 91.19,42.93 90.3,43.81 88.65,43.81 88.39,43.56
DGND on TOP: 21.77,32.59 22.1,32.26 22.23,32.26 22.24,32.27 24.27,32.27 24.59,31.95 24.59,6.9 24.05,6.36 6.96,6.36 5.08,8.24 5.08,19.08 4.38,19.78 3.25,19.78 3.25,30.86 3.68,31.29 12.8,31.29 12.83,31.27 14.12,32.56 14.12,32.59
DGND on TOP: 30.95,37.54 30.95,36.42 31.51,35.86 31.51,35.48 31.64,35.35 31.66,35.35 31.71,35.3 32.55,35.3 32.68,35.43 32.68,35.76 32.32,36.11 32.27,36.11 32.25,36.14 32.25,37.66 32.2,37.71 31.13,37.71
DGND on TOP: 32,44.83 32,43.69 32.38,43.31 48.39,43.31 48.64,43.56 48.64,44.83 48.26,45.21 32.38,45.21
DGND on TOP: 74.78,17.02 75.34,16.46 75.34,13.28 75.04,12.98 74.55,12.98 73.63,12.06 72.52,12.06 71.63,12.95 71.63,12.98 70.19,12.98 68,10.79 68,7.75 69.53,6.22 71.15,6.22 71.15,6.43 71.23,6.5 71.96,6.5 72.24,6.22 74.1,6.22 74.61,5.71 76.07,5.71 78.99,2.79 78.99,2.67 66.93,2.67 63.99,5.61 63.99,8.28 64.57,8.86 64.57,11.05 64.07,11.56 63.25,11.56 62.99,11.81 62.99,15.24 64.77,17.02 ; 1 cut-out
DGND on TOP: 78.83,4.31 78.96,4.45 82.56,4.45 82.56,3.35 83.08,2.83 83.31,2.83 83.31,1.14 79.49,1.14 78.83,1.8
DGND on BOTTOM: 119.25,20.83 119.25,23.75 121.03,25.53 123.06,25.53 123.57,25.02 123.57,20.7 123.32,20.45 119.63,20.45
DGND on BOTTOM: 120.65,15.75 120.65,13.94 121.02,13.58 124.19,13.58 124.46,13.84 124.46,15.49 123.95,16 120.9,16
DGND on BOTTOM: 97.32,51.96 97.32,47.32 98.29,46.35 105.55,46.35 105.98,46.78 105.98,51.68 105.22,52.45 97.8,52.45
DGND on BOTTOM: 128,37.69 128,36.95 127.62,36.57 127.62,34.74 127.83,34.54 130.75,34.54 130.98,34.77 130.98,37.77 130.77,37.97 128.28,37.97
DGND on BOTTOM: 46.88,63.17 46.88,60.57 46.72,60.73 46.42,60.73 46.29,60.6 46.29,60.24 46.37,60.24 46.88,59.74 46.88,58.34 47.77,57.45 51.22,57.45 51.88,58.11 51.88,63.22 51.42,63.67 47.44,63.67 46.93,63.17
DGND on BOTTOM: 72.95,14.22 72.83,14.22 72.07,14.99 72.07,17.27 74.27,19.48 77.95,19.48 80.19,21.72 87.31,21.72 89.97,24.38 95.33,24.38 95.21,24.26 98.17,24.26 98.93,23.49 98.93,21.81 97.31,20.19 91.24,20.19 90.47,19.43 89.84,19.43 89.5,19.08 89.15,18.74 89.15,18.03 89.03,17.91 88.14,17.91 88.17,17.88 80.84,17.88 79.47,16.51 76.64,16.51 75.42,15.29 75.42,13.72 74.73,13.03 74.14,13.03
DGND on BOTTOM: 12.95,31.22 12.95,32.39 13.16,32.59 23.95,32.59 23.98,32.61 24.94,32.61 25.88,31.67 25.88,21.76 25.81,21.69 25.81,21.36 24.6,20.15 24.6,6.9 24.04,6.35 7.1,6.35 5.07,8.38 5.07,18.28 3.47,19.88 3.28,19.88 3.28,30.94 3.56,31.22
DGND on BOTTOM: 56.83,0.64 55.77,1.7 55.77,5.96 54.52,7.21 54.52,11.04 54.52,17.82 55.69,18.99 55.69,21.76 55.68,21.78 55.68,22.41 55.77,22.5 55.77,25.3 56.27,25.8 58.7,25.8 59.18,25.32 59.18,19.18 58.91,18.9 58.91,18.07 58.74,17.91 58.74,17.9 58.38,17.55 58.38,12.44 59.75,11.07 59.75,8.1 63.89,3.96 65.85,3.96 66.51,4.62 83.68,4.62 84.72,3.58 84.72,2.21 85.08,1.85 85.08,1.57 105.02,1.57 107.06,3.62 118.52,3.62 119.27,2.87 119.27,1.09 110.38,1.09 110.38,0.64
DGND on BOTTOM: 115.58,31.31 115.58,29.66 114.06,28.14 114.06,27.76 114.31,27.5 116.09,27.5 117.11,28.52 117.11,32.58 116.85,32.84 115.33,32.84 115.08,32.58 115.08,31.82
DGND on BOTTOM: 64.16,15.69 64.83,16.36 64.83,19.75 64.28,20.3 63.04,20.3 62.88,20.14 62.88,18.26 61.99,17.37 62.02,17.37 61.74,17.09 61.74,15.82 61.86,15.69
DGND on BOTTOM: 111.76,41.55 115.93,41.55 115.93,41.02 116.2,40.74 117.43,40.74 117.43,40.54 116.18,40.54 115.93,40.28 115.93,40.16 116.15,39.93 117.5,39.93 117.5,39.75 116.13,39.75 115.93,39.55 115.93,37.36 115.9,37.34 111.81,37.34 111.73,37.41 111.73,41.53
DGND on BOTTOM: 47.64,35.33 47.77,35.2 49.14,35.2 49.54,35.61 49.54,40.71 49.09,41.17 46.52,41.17 46.19,41.5 44.21,41.5 44.21,41.47 43.9,41.17 43.7,41.17 43.35,41.52 42.46,41.52 41.92,40.99 41.92,35.81 42.41,35.33
DGND on BOTTOM: 105.79,22.73 105.79,18.47 105.5,18.18 101.79,18.18 100.58,19.39 100.58,22.73 101.34,23.49 105.04,23.49
DGND on BOTTOM: 20.02,45.54 15.45,45.54 15.32,45.67 15.32,46.05 15.45,46.18 19.64,46.18 20.02,45.8
DGND on LY2_GND1: 123.82,0.63 7.91,0.63 7.91,3.76 7.12,6.16 5.01,7.58 5.01,18.89 5.07,18.94 4.31,19.71 0.63,19.71 0.63,63.29 3.95,63.29 6.75,64.45 7.91,67.25 7.91,70.38 99.07,70.38 99.67,69.78 110.79,69.78 111.39,70.38 123.82,70.38 123.82,67.25 124.97,64.45 127.78,63.29 132.88,63.29 132.88,7.72 127.78,7.72 124.97,6.56 123.82,3.76
DGND on LY7_GND2: 123.82,0.63 7.91,0.63 7.91,3.76 7.22,6.03 5.34,7.48 5.09,7.73 5.09,18.97 4.26,19.81 0.63,19.81 0.63,63.29 3.95,63.29 6.75,64.45 7.91,67.25 7.91,70.38 99.07,70.38 99.67,69.78 110.79,69.78 111.39,70.38 123.82,70.38 123.82,67.25 124.97,64.45 127.78,63.29 132.88,63.29 132.88,7.72 127.78,7.72 124.97,6.56 123.82,3.76
GND_IN on TOP: 111.3,12.16 114.92,12.16 116.14,10.95 116.14,6.41 114.68,4.95 112.17,4.95 108.89,4.95 103.89,9.96 103.89,14.29 105.22,15.62 108.97,15.62 110.62,13.97 110.62,12.85
GND_IN on BOTTOM: 106.05,6.35 108.33,4.06 115.57,4.06 117.98,6.48 117.98,11.99 120.08,14.09 120.08,15.85 119.85,16.08 117.93,16.08 116.2,14.35 116.2,13.34 114.3,11.43 112.01,11.43 108.76,14.68 106.38,14.68 105.47,13.78 105.47,11.35 105.75,11.07 105.75,10.66 106.05,10.37
GNDA_ADC on TOP: 80.47,31.39 78.26,31.39 77.98,31.67 77.48,31.67 77.3,31.5 77.3,31.27 77.31,31.26 77.31,30.62 77.84,30.09 80.31,30.09 82.45,27.94 84.89,27.94 85.06,28.11 85.06,29.55 84.82,29.79 82.08,29.79
GNDA_TSC on BOTTOM: 80.53,31.57 81.17,32.2 83.07,32.2 83.33,32.46 83.33,33.35 83.2,33.47 82.94,33.47 82.44,32.96 81.29,32.96 81.04,32.71 80.53,32.71 80.4,32.84 80.28,32.84 79.77,32.33 79.52,32.33 79.01,32.84 78.63,32.84 78.5,32.71 78.5,32.58 78.75,32.33 78.75,32.08 78.5,31.82 78.5,31.69 78.63,31.57
V1_8D on TOP: 28.78,15.32 28.78,12.52 29.17,12.14 29.17,10.36 30.18,10.36 30.18,12.14 30.44,12.4 30.44,15.32 30.18,15.57 29.04,15.57
V1_8D on BOTTOM: 16.47,38.56 16.47,43.51 16.72,43.76 18.5,43.76 18.88,43.38 18.88,38.56 19.77,37.67 20.15,37.67 20.28,37.54 20.53,37.54 20.66,37.41 20.66,36.91 20.53,36.78 15.7,36.78 15.2,37.29 15.2,38.18 15.32,38.3 15.83,38.3 15.96,38.43 16.34,38.43
V1_8D on LYR4_PWR1: 20.02,39.32 23.32,36.02 23.32,23.87 25.66,21.54 33.63,21.54 39.62,15.54 42.03,15.54 48.45,21.97 51.22,21.97 52.69,20.49 52.69,8.78 51.5,7.59 46.45,7.59 46.45,7.59 45.05,7.59 42.63,5.17 42.63,1.38 42.14,0.89 8.98,0.89 8.15,1.71 8.15,6.45 6.48,8.13 5.17,8.13 5.17,19.96 5.09,20.04 0.89,20.04 0.89,39 1.21,39.32
V3_3AUD on TOP: 46.18,6.02 46.23,5.97 46.36,5.97 46.48,6.1 46.48,7.62 46.18,7.92 46.18,8.64 45.8,9.02 43.94,9.02 43,8.08 39.99,8.08 39.22,8.84 34.88,8.84 34.63,8.59 34.63,6.27 34.88,6.02
V3_3AUD on BOTTOM: 34.82,9.5 34.82,7.29 35.05,7.06 36.93,7.06 37.22,7.35 37.21,7.37 37.21,9.14 36.79,9.56 35.67,9.56 35.56,9.68 35,9.68
V3_3AUD on BOTTOM: 40.49,7.57 40.16,7.24 40.16,6.55 40.34,6.38 41.3,6.38 41.53,6.6 41.53,7.04 41.17,7.39 41.17,9.17 40.51,9.17 40.49,9.14
V3_3D on TOP: 112.45,52.36 112.45,48.44 112.73,48.16 114.48,48.16 114.79,48.46 114.79,49.86 114.81,49.88 114.81,50.04 114.68,50.17 113.87,50.17 113.47,50.57 113.47,52.37 113.33,52.51 112.6,52.51
V3_3D on BOTTOM: 51.94,31.18 51.94,27.69 51.95,27.68 51.95,27.54 52.28,27.2 54.39,27.2 54.79,27.61 54.79,28.86 54.62,29.03 54.24,29.03 53.91,29.37 53.91,30.99 53.52,31.37 52.13,31.37
V3_3D on LYR4_PWR1: 0.89,47.95 0.89,62.68 1.25,63.04 3.95,63.04 6.93,64.28 8.16,67.25 8.16,69.49 8.8,70.12 98.96,70.12 99.56,69.52 110.9,69.52 111.5,70.12 123.11,70.12 123.56,69.67 123.56,67.25 124.8,64.28 127.78,63.04 132.22,63.04 132.63,62.63 132.63,8.3 132.29,7.97 127.78,7.97 124.8,6.73 123.56,3.76 123.56,0.99 123.25,0.68 88.76,0.68 88.53,0.91 88.53,15.44 91.71,18.61 118.5,18.61 120.54,20.65 120.54,30.3 124.09,33.85 124.09,38.17 122.95,39.31 109.06,39.31 108.78,39.59 108.78,42.06 106.86,43.97 93.27,43.97 91.71,45.54 69.81,45.54 63.77,39.49 63.77,30.68 59.37,26.28 59.37,16.12 58.87,15.62 58.87,10.08 60.27,8.67 60.27,1.28 59.89,0.89 44.33,0.89 43.88,1.34 43.88,4.87 45.94,6.93 50.99,6.93 53.02,8.96 53.02,20.39 51.12,22.3 51.17,22.3 50.92,22.55 48.11,22.55 41.77,16.21 39.9,16.21 34.07,22.04 32.55,22.04 32.04,22.55 32.04,43.33 27.7,47.68 1.16,47.68
V5_0D on TOP: 14.31,49.35 14.31,48.21 15.83,46.69 18.88,46.69 19.39,47.19 19.39,48.84 19.13,49.1 18.75,49.1 18.24,49.61 14.56,49.61
V5_0D on BOTTOM: 14.81,50.32 14.81,48.05 16.31,46.56 19.89,46.56 20.4,46.05 22.94,46.05 23.07,46.18 23.07,47.07 22.82,47.32 21.8,47.32 21.55,47.07 20.78,47.07 19.79,48.06 17.13,48.06 16.97,48.21 16.97,50.34 16.81,50.5 14.99,50.5
VBAT on TOP (solid shape): 25.86,50.75 25.86,49.86 25.61,49.61 23.81,49.61 23.58,49.38 22.29,49.38 22.05,49.61 22.05,50.88 22.31,51.13 25.48,51.13
VBAT on BOTTOM (solid shape): 23.83,51.89 23.83,50.59 23.47,50.22 23.31,50.22 23.3,50.21 23,50.21 22.54,49.75 22.54,49.5 22.47,49.42 21.92,49.42 21.92,49.52 21.92,49.82 22.05,49.95 22.05,50.23 22.06,50.24 22.12,50.5 22.05,50.76 22.05,51.25 22.06,51.27 22.13,51.33 22.21,51.31 22.71,51.36 22.74,51.86 22.73,51.96 22.82,52.02 23.7,52.02
VBAT on TOP: 118.93,33.66 118.93,37.36 118.63,37.66 118.33,37.66 117.37,36.7 111.86,36.7 111.37,36.21 111.37,35.46 111.05,35.15 111.05,34.7 111.33,34.42 113.44,34.42 114.76,33.09 118.37,33.09
VBAT on TOP: 110.93,52.27 110.93,50.47 110.24,49.78 110.24,49.28 110.11,49.15 108.36,49.15 108.2,49.31 108.2,50.29 108.39,50.47 109.79,50.47 109.91,50.6 109.91,52.25 109.98,52.32 110.87,52.32
VBAT on TOP: 109.22,20.07 109.6,19.69 116.2,19.69 116.33,19.81 117.47,19.81 117.73,20.07 117.73,25.53 117.09,26.16 113.54,26.16 112.52,27.18 109.73,27.18 109.22,26.67 109.22,21.72 109.09,21.59 109.09,20.7 109.22,20.57
VBAT on TOP: 26.24,42.05 26.24,44.15 25.86,44.53 24.47,44.53 24.21,44.27 24.21,40.77 24.65,40.34 25.86,40.34 25.99,40.46 25.99,41.8
VBAT on TOP: 31.71,10.36 31.71,14.94 31.83,15.06 33.1,15.06 33.36,14.81 33.36,13.79 32.59,13.03 32.59,12.27 32.72,12.14 32.72,10.49 32.59,10.36
